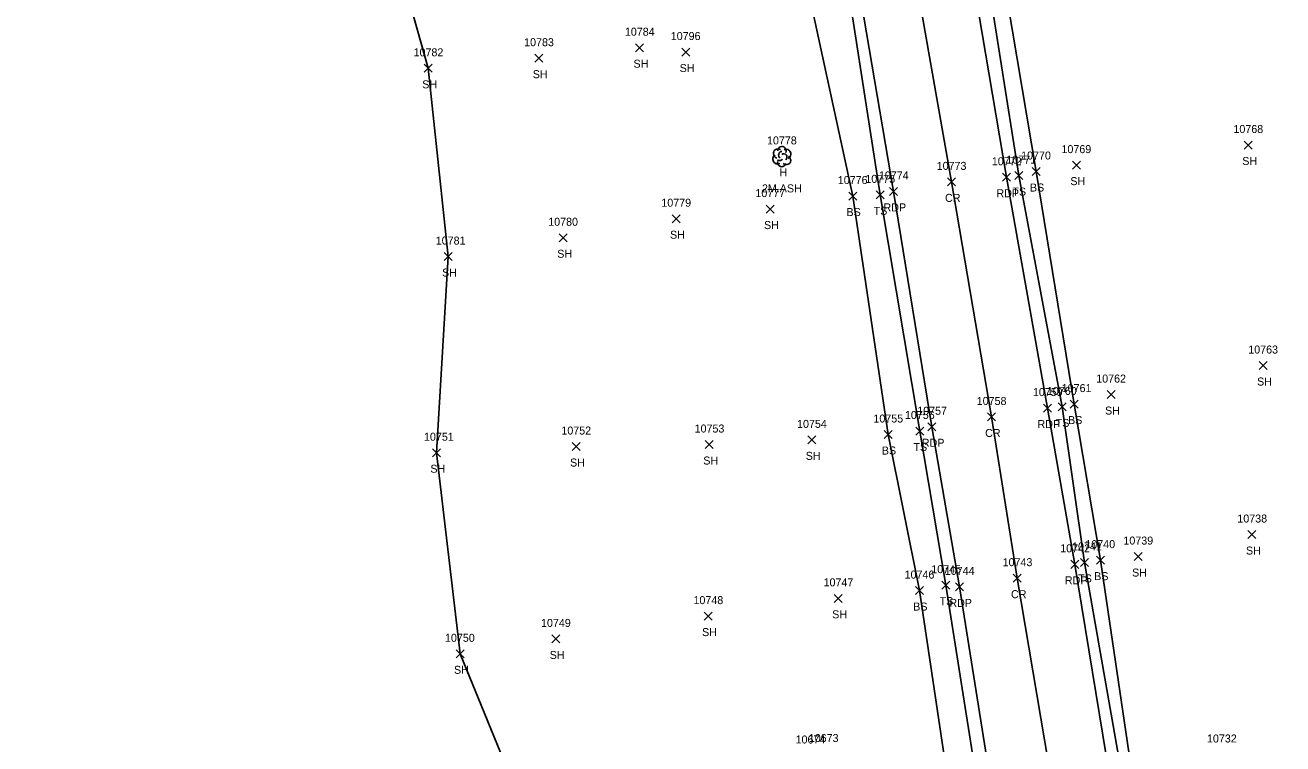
# Model space of a CAD drawing. Extents: x 1439173 to 1457902, y 641926 to 659889.
# Drawn here: x 1447859 to 1448173.4, y 647473 to 647652.7 of the extents above; entities that cross this region are included whole.
import ezdxf

# ---------------------------------------------------------------- set-up
doc = ezdxf.new("R2010")
doc.units = 0
for name, color, linetype in [('L_A', 7, 'Continuous'), ('L_C', 7, 'Continuous'), ('L_I', 7, 'Continuous'), ('L_TIC', 7, 'Continuous'), ('LELB', 7, 'Continuous'), ('LSOGP', 7, 'Continuous'), ('LTD', 7, 'Continuous'), ('P_A', 7, 'Continuous'), ('P_I', 7, 'Continuous'), ('P_TIC', 7, 'Continuous'), ('PET', 7, 'Continuous'), ('PRC', 7, 'Continuous')]:
    doc.layers.add(name, color=color, linetype=linetype)

msp = doc.modelspace()

# ---------------------------------------------------------------- linework, layer by layer
at = {"layer": 'L_TIC'}
for points in [[(1448011.62, 647646.05), (1448013.62, 647648.05)], [(1448013.62, 647646.05), (1448011.62, 647648.05)], [(1447986.43, 647643.43), (1447988.43, 647645.43)], [(1447988.43, 647643.43), (1447986.43, 647645.43)], [(1448023.15, 647644.97), (1448025.15, 647646.97)], [(1448025.15, 647644.97), (1448023.15, 647646.97)], [(1447958.81, 647640.9), (1447960.81, 647642.9)], [(1447960.81, 647640.9), (1447958.81, 647642.9)], [(1448163.78, 647621.73), (1448165.78, 647623.73)], [(1448165.78, 647621.73), (1448163.78, 647623.73)], [(1448110.76, 647615.1), (1448112.76, 647617.1)], [(1448112.76, 647615.1), (1448110.76, 647617.1)], [(1448120.8, 647616.7), (1448122.8, 647618.7)], [(1448122.8, 647616.7), (1448120.8, 647618.7)], [(1448106.4, 647614.08), (1448108.4, 647616.08)], [(1448108.4, 647614.08), (1448106.4, 647616.08)], [(1448064.9, 647608.97), (1448066.9, 647610.97)], [(1448066.9, 647608.97), (1448064.9, 647610.97)], [(1448071.73, 647609.27), (1448073.73, 647611.27)], [(1448073.73, 647609.27), (1448071.73, 647611.27)], [(1448044.24, 647605.71), (1448046.24, 647607.71)], [(1448046.24, 647605.71), (1448044.24, 647607.71)], [(1448020.74, 647603.3), (1448022.74, 647605.3)], [(1448022.74, 647603.3), (1448020.74, 647605.3)], [(1447992.55, 647598.54), (1447994.55, 647600.54)], [(1447994.55, 647598.54), (1447992.55, 647600.54)], [(1447963.79, 647593.84), (1447965.79, 647595.84)], [(1447965.79, 647593.84), (1447963.79, 647595.84)], [(1448167.48, 647566.6), (1448169.48, 647568.6)], [(1448169.48, 647566.6), (1448167.48, 647568.6)], [(1448129.49, 647559.34), (1448131.49, 647561.34)], [(1448131.49, 647559.34), (1448129.49, 647561.34)], [(1448117.23, 647556.25), (1448119.23, 647558.25)], [(1448119.23, 647556.25), (1448117.23, 647558.25)], [(1448120.29, 647556.96), (1448122.29, 647558.96)], [(1448122.29, 647556.96), (1448120.29, 647558.96)], [(1448073.74, 647549.35), (1448075.74, 647551.35)], [(1448075.74, 647549.35), (1448073.74, 647551.35)], [(1448081.67, 647550.23), (1448083.67, 647552.23)], [(1448083.67, 647550.23), (1448081.67, 647552.23)], [(1447995.75, 647546.35), (1447997.75, 647548.35)], [(1447997.75, 647546.35), (1447995.75, 647548.35)], [(1448029.05, 647546.85), (1448031.05, 647548.85)], [(1448031.05, 647546.85), (1448029.05, 647548.85)], [(1448054.66, 647548.02), (1448056.66, 647550.02)], [(1448056.66, 647548.02), (1448054.66, 647550.02)], [(1447960.84, 647544.8), (1447962.84, 647546.8)], [(1447962.84, 647544.8), (1447960.84, 647546.8)], [(1448164.7, 647524.35), (1448166.7, 647526.35)], [(1448166.7, 647524.35), (1448164.7, 647526.35)], [(1448122.84, 647517.37), (1448124.84, 647519.37)], [(1448124.84, 647517.37), (1448122.84, 647519.37)], [(1448126.81, 647517.95), (1448128.81, 647519.95)], [(1448128.81, 647517.95), (1448126.81, 647519.95)], [(1448136.24, 647518.84), (1448138.24, 647520.84)], [(1448138.24, 647518.84), (1448136.24, 647520.84)], [(1448088.21, 647511.69), (1448090.21, 647513.69)], [(1448090.21, 647511.69), (1448088.21, 647513.69)], [(1448061.29, 647508.4), (1448063.29, 647510.4)], [(1448063.29, 647508.4), (1448061.29, 647510.4)], [(1448081.59, 647510.34), (1448083.59, 647512.34)], [(1448083.59, 647510.34), (1448081.59, 647512.34)], [(1448028.77, 647503.95), (1448030.77, 647505.95)], [(1448030.77, 647503.95), (1448028.77, 647505.95)], [(1447990.67, 647498.25), (1447992.67, 647500.25)], [(1447992.67, 647498.25), (1447990.67, 647500.25)], [(1447966.75, 647494.53), (1447968.75, 647496.53)], [(1447968.75, 647494.53), (1447966.75, 647496.53)]]:
    msp.add_lwpolyline(points, dxfattribs=at)
at = {"layer": 'LELB'}
for points in [[(1448133.2, 647465.28), (1448123.84, 647518.37), (1448118.23, 647557.25), (1448107.4, 647615.08), (1448098.25, 647673.15), (1448089.32, 647729.73), (1448079.58, 647780.87), (1448069.23, 647834.13), (1448063.64, 647869.54), (1448056.91, 647910.15), (1448054.25, 647926.71), (1448055.08, 647937.78), (1448059.77, 647944.56), (1448076.81, 647945.13), (1448083.52, 647949.95), (1448105.85, 647955.94), (1448131.02, 647955.93), (1448149.88, 647953.41), (1448168.49, 647958.59)], [(1448260.6, 647411.18), (1448224.21, 647406.67), (1448190.23, 647399.82), (1448162.27, 647393.34), (1448150.17, 647397.11), (1448143.67, 647427.29), (1448135.63, 647465.82), (1448127.81, 647518.95), (1448121.29, 647557.96), (1448111.76, 647616.1), (1448102.2, 647673.03), (1448093.89, 647725), (1448082.06, 647780.89), (1448072.55, 647837.45), (1448066.89, 647870.13), (1448059.83, 647910.84), (1448057.62, 647927.05), (1448057.68, 647936.79), (1448068.91, 647935.54), (1448077.77, 647925.68)], [(1448069.88, 647454.51), (1448081.92, 647458.76), (1448094.88, 647461.43), (1448096.31, 647467.37), (1448089.21, 647512.69), (1448082.67, 647551.23), (1448072.73, 647610.27), (1448064.94, 647660.74), (1448053.74, 647723.05), (1448045.09, 647774.78), (1448035.51, 647827.8), (1448028.47, 647862.62), (1448021.91, 647904.29), (1448017.86, 647930.03)], [(1448075.24, 647462.58), (1448089.36, 647466.11), (1448082.59, 647511.34), (1448074.74, 647550.35), (1448065.9, 647609.97), (1448055.44, 647658.33)]]:
    msp.add_lwpolyline(points, dxfattribs=at)
at = {"layer": 'LSOGP'}
msp.add_lwpolyline([(1447987.81, 647446.65), (1447967.75, 647495.54), (1447961.84, 647545.81), (1447964.79, 647594.85), (1447959.81, 647641.91), (1447949.67, 647677.74), (1447948.02, 647705.64), (1447943.28, 647719.48), (1447936.79, 647750.06), (1447919.97, 647760.22), (1447915.3, 647770.51), (1447913.14, 647792.01), (1447904.13, 647829.96), (1447902.1, 647844.59), (1447898.24, 647862.14), (1447896.82, 647871.81), (1447895.41, 647881.47), (1447893.62, 647897.34), (1447892.54, 647905.84), (1447892.82, 647906.76), (1447890.35, 647931.54), (1447889.29, 647943.84), (1447859.05, 647978.72)], dxfattribs=at)
at = {"layer": 'LTD'}
msp.add_line((1448048.15, 647619.88), (1448048.15, 647619.88), dxfattribs=at)
msp.add_line((1448048.15, 647619.88), (1448048.15, 647619.88), dxfattribs=at)
msp.add_arc((1448048.2, 647621.32), 1.05, 335.5272, 180.9563, dxfattribs=at)
for centre, major_axis, ratio, start_param, end_param in [((1448047.07, 647619.18), (0.58, -1.04), 0.959034, 3.141593, 6.283185), ((1448047.36, 647620.55), (1.21, -0.51), 0.895232, 1.570796, 4.712389), ((1448047.94, 647620.34), (-0.208, -0.792), 0.645439, 3.141593, 6.283185), ((1448048.65, 647619.72), (-0.5, 0.667), 0.989748, 3.141593, 6.283185), ((1448049.15, 647619.05), (-1.09, 0.79), 0.841452, 1.570796, 4.712389), ((1448049.19, 647620.47), (-1.14, -0.48), 0.949671, 1.570796, 4.712389), ((1448048.15, 647618.38), (0.26, 1.06), 0.942809, 1.570796, 4.712389), ((1448047.69, 647619.13), (-0.625, -0.083), 0.423636, 0, 3.141593)]:
    msp.add_ellipse(centre, major_axis=major_axis, ratio=ratio, start_param=start_param, end_param=end_param, dxfattribs=at)
at = {"layer": 'P_TIC'}
for points in [[(1448089.56, 647612.51), (1448091.56, 647614.51)], [(1448091.56, 647612.51), (1448089.56, 647614.51)], [(1448103.34, 647613.66), (1448105.34, 647615.66)], [(1448105.34, 647613.66), (1448103.34, 647615.66)], [(1448075.11, 647610.13), (1448077.11, 647612.13)], [(1448077.11, 647610.13), (1448075.11, 647612.13)], [(1448113.61, 647555.96), (1448115.61, 647557.96)], [(1448115.61, 647555.96), (1448113.61, 647557.96)], [(1448099.57, 647553.74), (1448101.57, 647555.74)], [(1448101.57, 647553.74), (1448099.57, 647555.74)], [(1448084.69, 647551.29), (1448086.69, 647553.29)], [(1448086.69, 647551.29), (1448084.69, 647553.29)], [(1448120.44, 647516.9), (1448122.44, 647518.9)], [(1448122.44, 647516.9), (1448120.44, 647518.9)], [(1448091.58, 647511.26), (1448093.58, 647513.26)], [(1448093.58, 647511.26), (1448091.58, 647513.26)], [(1448106.04, 647513.44), (1448108.04, 647515.44)], [(1448108.04, 647513.44), (1448106.04, 647515.44)]]:
    msp.add_lwpolyline(points, dxfattribs=at)
at = {"layer": 'PET'}
for points in [[(1448100.59, 647462), (1448092.58, 647512.26), (1448085.69, 647552.29), (1448076.11, 647611.13), (1448066.63, 647666.99), (1448057.22, 647723.26), (1448048.8, 647775.44), (1448039.96, 647828.22), (1448033.77, 647863.81), (1448026.88, 647905.01), (1448021.4, 647936.06), (1448017.51, 647960.41), (1448010.89, 648001.49)], [(1448130.19, 647464.52), (1448121.44, 647517.9), (1448114.61, 647556.96), (1448104.34, 647614.66), (1448094.66, 647671.87), (1448085.04, 647729.14), (1448076.47, 647780.94), (1448067.53, 647833.9), (1448061.43, 647869.79), (1448054.63, 647910.26)]]:
    msp.add_lwpolyline(points, dxfattribs=at)
at = {"layer": 'PRC'}
msp.add_lwpolyline([(1448115.84, 647462.16), (1448107.04, 647514.44), (1448100.57, 647554.74), (1448090.56, 647613.51), (1448080.63, 647670.41), (1448071.72, 647726.68), (1448062.75, 647778.56), (1448054.69, 647830.39), (1448047.71, 647867.06), (1448041.1, 647908.04), (1448036.61, 647937.95), (1448032.33, 647961.7), (1448025.03, 648003.46)], dxfattribs=at)

# ---------------------------------------------------------------- texts
at = {"layer": 'L_A'}
for s, p in [('SH', (1448011.11, 647642.05)), ('SH', (1448022.64, 647640.97)), ('SH', (1447958.3, 647636.9)), ('SH', (1447985.92, 647639.43)), ('SH', (1448163.27, 647617.73)), ('H', (1448047.58, 647614.88)), ('SH', (1448120.29, 647612.7)), ('TS', (1448105.81, 647610.08)), ('BS', (1448110.2, 647611.1)), ('BS', (1448064.34, 647604.97)), ('TS', (1448071.14, 647605.27)), ('SH', (1448020.23, 647599.3)), ('SH', (1448043.73, 647601.71)), ('SH', (1447992.04, 647594.54)), ('SH', (1447963.27, 647589.84)), ('SH', (1448166.97, 647562.6)), ('SH', (1448128.97, 647555.34)), ('TS', (1448116.64, 647552.25)), ('BS', (1448119.73, 647552.96)), ('BS', (1448073.18, 647545.35)), ('TS', (1448081.08, 647546.23)), ('SH', (1447995.24, 647542.35)), ('SH', (1448028.54, 647542.85)), ('SH', (1448054.15, 647544.02)), ('SH', (1447960.33, 647540.8)), ('SH', (1448164.19, 647520.35)), ('BS', (1448126.25, 647513.95)), ('SH', (1448135.73, 647514.84)), ('TS', (1448122.25, 647513.37)), ('TS', (1448087.62, 647507.69)), ('SH', (1448060.77, 647504.4)), ('BS', (1448081.03, 647506.34)), ('SH', (1448028.25, 647499.95)), ('SH', (1447990.16, 647494.25)), ('SH', (1447966.24, 647490.53))]:
    msp.add_text(s, height=2, dxfattribs=at).set_placement(p)
at = {"layer": 'L_C'}
msp.add_text('2M.ASH', height=2, dxfattribs=at).set_placement((1448043.21, 647610.88))
at = {"layer": 'L_I'}
for s, p in [('10784', (1448008.95, 647650.05)), ('10796', (1448020.42, 647648.97)), ('10783', (1447983.77, 647647.43)), ('10782', (1447956.14, 647644.9)), ('10768', (1448161.06, 647625.73)), ('10778', (1448044.48, 647622.88)), ('10769', (1448118.08, 647620.7)), ('10771', (1448104.3, 647618.08)), ('10770', (1448108, 647619.1)), ('10776', (1448062.17, 647612.97)), ('10775', (1448069.06, 647613.27)), ('10777', (1448041.57, 647609.71)), ('10779', (1448018.07, 647607.3)), ('10780', (1447989.79, 647602.54)), ('10781', (1447961.68, 647597.84)), ('10763', (1448164.77, 647570.6)), ('10761', (1448118.14, 647560.96)), ('10762', (1448126.77, 647563.34)), ('10760', (1448114.43, 647560.25)), ('10754', (1448051.99, 647552.02)), ('10755', (1448071.07, 647553.35)), ('10756', (1448078.95, 647554.23)), ('10751', (1447958.74, 647548.8)), ('10752', (1447993.08, 647550.35)), ('10753', (1448026.38, 647550.85)), ('10738', (1448162.04, 647528.35)), ('10741', (1448120.73, 647521.37)), ('10740', (1448124.05, 647521.95)), ('10739', (1448133.56, 647522.84)), ('10746', (1448078.87, 647514.34)), ('10745', (1448085.54, 647515.69)), ('10747', (1448058.62, 647512.4)), ('10748', (1448026.1, 647507.95)), ('10749', (1447987.99, 647502.25)), ('10750', (1447963.99, 647498.53)), ('10674', (1448051.62, 647473.11)), ('10673', (1448054.92, 647473.48)), ('10732', (1448154.45, 647473.36))]:
    msp.add_text(s, height=2, dxfattribs=at).set_placement(p)
at = {"layer": 'P_A'}
for s, p in [('CR', (1448088.99, 647608.51)), ('RDP', (1448101.83, 647609.66)), ('RDP', (1448073.6, 647606.13)), ('RDP', (1448112.1, 647551.96)), ('CR', (1448099, 647549.74)), ('RDP', (1448083.18, 647547.29)), ('RDP', (1448118.93, 647512.9)), ('CR', (1448105.47, 647509.44)), ('RDP', (1448090.06, 647507.26))]:
    msp.add_text(s, height=2, dxfattribs=at).set_placement(p)
at = {"layer": 'P_I'}
for s, p in [('10772', (1448100.67, 647617.66)), ('10773', (1448086.89, 647616.51)), ('10774', (1448072.44, 647614.13)), ('10758', (1448096.9, 647557.74)), ('10759', (1448110.93, 647559.96)), ('10757', (1448082.02, 647555.29)), ('10742', (1448117.77, 647520.9)), ('10743', (1448103.37, 647517.44)), ('10744', (1448088.91, 647515.26))]:
    msp.add_text(s, height=2, dxfattribs=at).set_placement(p)

doc.saveas('drawing.dxf')
